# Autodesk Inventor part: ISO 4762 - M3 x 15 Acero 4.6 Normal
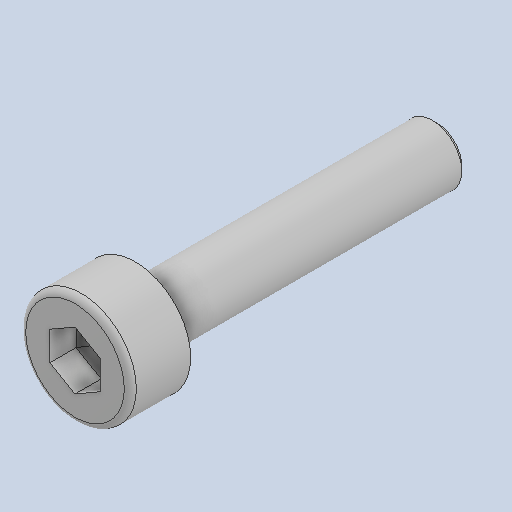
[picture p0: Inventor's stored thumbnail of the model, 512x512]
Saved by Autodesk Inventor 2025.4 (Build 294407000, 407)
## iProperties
Created: 2026-09
Part Number: ISO 4762 - M3 x 15 Acero 4.6 Normal
Material: Generic
Description: Tornillo de cabeza hexagonal hueca ISO 4762 - M3 x 15
Document SubType Name: Modeling
Designer: AdminForWorker
Density: 1 g/cm^3
Appearance: Default
Title: Tornillo de cabeza hexagonal hueca ISO 4762 - M3 x 15 Acero 4.6 Normal v1
Author: AdminForWorker
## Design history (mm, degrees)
feature "Body1"
body "Solid1"
